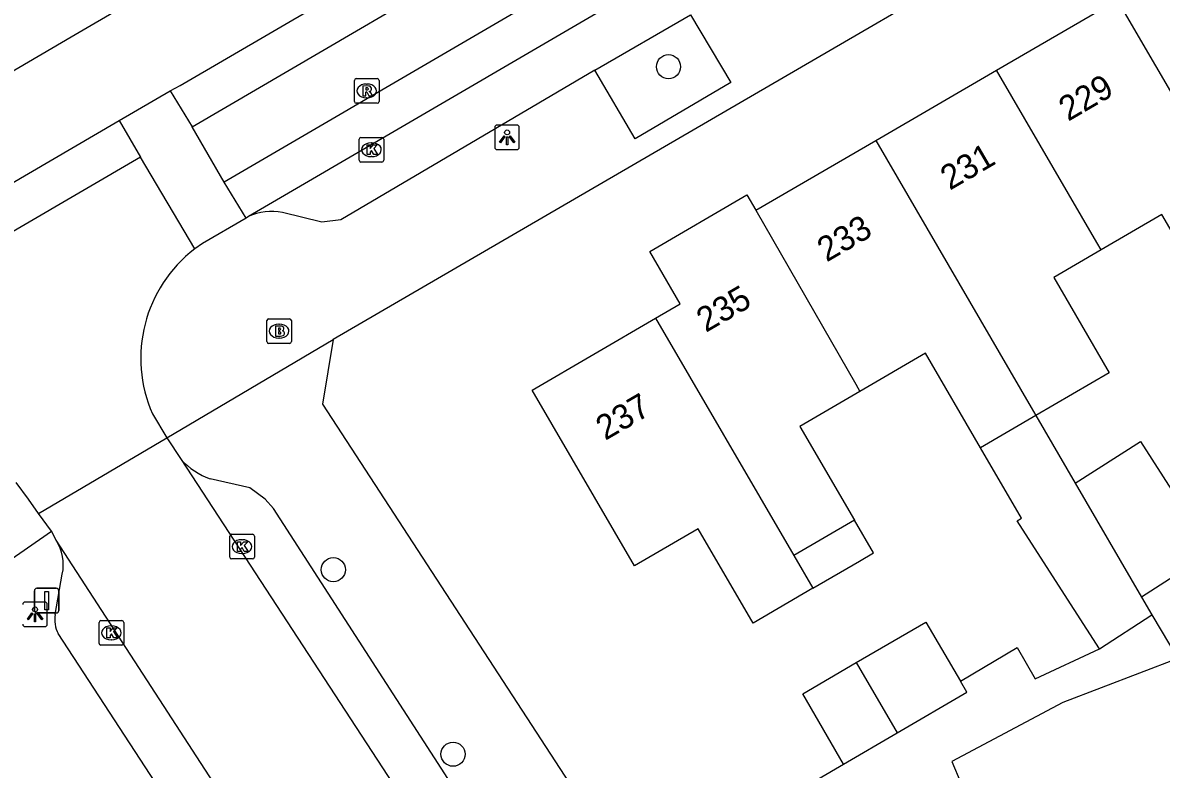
# Model space of a CAD drawing. Extents: x 158352 to 159489, y 383828 to 384597.
# Drawn here: x 158638.04 to 158684.3, y 384076.1 to 384106.43 of the extents above; entities that cross this region are included whole.
import ezdxf

# ---------------------------------------------------------------- set-up
doc = ezdxf.new("R2010")
doc.units = 0
for name, color, linetype in [('IMGEO_Afsluitpaal', 7, 'Continuous'), ('IMGEO_Boom', 7, 'Continuous'), ('IMGEO_Brandkraan', 7, 'Continuous'), ('IMGEO_Kolk', 7, 'Continuous'), ('IMGEO_Lichtpunt', 7, 'Continuous'), ('IMGEO_Pand', 7, 'Continuous'), ('IMGEO_Pand_nummerreeks', 7, 'Continuous'), ('IMGEO_Pand_overbouw', 7, 'Continuous'), ('IMGEO_Parkeervlak_open', 7, 'Continuous'), ('IMGEO_Rijbaan_lokaal_gesloten', 7, 'Continuous'), ('IMGEO_Rijbaan_lokaal_open', 7, 'Continuous'), ('IMGEO_Rioolput', 7, 'Continuous'), ('IMGEO_Voetpad_open', 7, 'Continuous')]:
    doc.layers.add(name, color=color, linetype=linetype)

msp = doc.modelspace()

# ---------------------------------------------------------------- linework, layer by layer
at = {"layer": 'IMGEO_Afsluitpaal'}
for p, q in [((158638.51, 384082.555), (158638.51, 384083.355)), ((158638.51, 384083.355), (158638.51, 384082.555)), ((158638.61, 384083.455), (158639.4, 384083.455)), ((158639.4, 384083.455), (158638.61, 384083.455)), ((158639.5, 384083.355), (158639.5, 384082.555)), ((158639.5, 384082.555), (158639.5, 384083.355)), ((158639.4, 384082.455), (158638.61, 384082.455)), ((158638.61, 384082.455), (158639.4, 384082.455))]:
    msp.add_line(p, q, dxfattribs=at)
msp.add_lwpolyline([(158638.93, 384083.33), (158639.08, 384083.33), (158639.08, 384082.58), (158638.93, 384082.58), (158638.93, 384083.33)], dxfattribs=at)
for centre, start, end in [((158638.61, 384083.355), 90, 180), ((158638.61, 384083.355), 90, 180), ((158639.4, 384083.355), 0, 90), ((158639.4, 384083.355), 360, 90), ((158638.61, 384082.555), 180, 270), ((158638.61, 384082.555), 180, 270), ((158639.4, 384082.555), 270, 0), ((158639.4, 384082.555), 270, 0)]:
    msp.add_arc(centre, 0.1, start, end, dxfattribs=at)
at = {"layer": 'IMGEO_Boom'}
for centre in [(158664.28, 384104.644), (158650.658, 384084.211), (158655.523, 384076.714)]:
    msp.add_circle(centre, 0.489, dxfattribs=at)
at = {"layer": 'IMGEO_Brandkraan'}
for p, q in [((158647.954, 384093.476), (158647.954, 384094.328)), ((158648.029, 384094.402), (158648.881, 384094.402)), ((158648.955, 384094.328), (158648.955, 384093.476)), ((158648.442, 384094.182), (158648.467, 384094.182)), ((158648.881, 384093.402), (158648.029, 384093.402)), ((158648.465, 384093.622), (158648.44, 384093.622))]:
    msp.add_line(p, q, dxfattribs=at)
for points in [[(158647.954, 384093.476), (158647.954, 384094.328)], [(158648.029, 384094.402), (158648.881, 384094.402)], [(158648.955, 384094.328), (158648.955, 384093.476)], [(158648.302, 384094.102), (158648.302, 384093.702), (158648.515, 384093.702)], [(158648.533, 384094.102), (158648.302, 384094.102)], [(158648.481, 384094.021), (158648.427, 384094.021), (158648.427, 384093.945)], [(158648.427, 384093.945), (158648.48, 384093.945)], [(158648.489, 384093.869), (158648.427, 384093.869), (158648.427, 384093.788)], [(158648.427, 384093.788), (158648.489, 384093.788)], [(158648.881, 384093.402), (158648.029, 384093.402)]]:
    msp.add_lwpolyline(points, dxfattribs=at)
for centre, radius, start, end in [((158648.031, 384094.326), 0.0765, 91.552, 178.448), ((158648.031, 384094.326), 0.0765, 91.552, 178.448), ((158648.879, 384094.326), 0.0765, 1.552, 88.448), ((158648.879, 384094.326), 0.0765, 1.552, 88.448), ((158648.482, 384093.983), 0.0379, 267.8285, 90.9355), ((158648.49, 384093.828), 0.0404, 269.8759, 90.5077), ((158648.537, 384093.957), 0.145, 59.4692, 91.5367), ((158648.562, 384094.004), 0.0922, 285.5137, 58.1501), ((158648.567, 384093.812), 0.105, 301.3115, 78.989), ((158648.031, 384093.478), 0.0765, 181.552, 268.448), ((158648.031, 384093.478), 0.0765, 181.552, 268.448), ((158648.521, 384093.953), 0.251, 268.6676, 293.5347), ((158648.879, 384093.478), 0.0765, 271.552, 358.448), ((158648.879, 384093.478), 0.0765, 271.552, 358.448)]:
    msp.add_arc(centre, radius, start, end, dxfattribs=at)
for centre, major_axis, ratio, start_param, end_param in [((158648.441, 384093.902), (-0.387, 0.002), 0.722429, 4.712389, 7.853982), ((158648.466, 384093.902), (-0.39, 0.002), 0.717154, 1.570796, 4.712389)]:
    msp.add_ellipse(centre, major_axis=major_axis, ratio=ratio, start_param=start_param, end_param=end_param, dxfattribs=at)
at = {"layer": 'IMGEO_Kolk'}
for p, q in [((158651.707, 384100.846), (158651.707, 384101.698)), ((158651.782, 384101.772), (158652.634, 384101.772)), ((158652.708, 384101.698), (158652.708, 384100.846)), ((158652.195, 384101.552), (158652.22, 384101.552)), ((158652.634, 384100.772), (158651.782, 384100.772)), ((158652.218, 384100.992), (158652.193, 384100.992)), ((158646.447, 384084.722), (158646.447, 384085.574)), ((158646.522, 384085.648), (158647.374, 384085.648)), ((158647.448, 384085.574), (158647.448, 384084.722)), ((158646.935, 384085.428), (158646.96, 384085.428)), ((158647.374, 384084.648), (158646.522, 384084.648)), ((158646.958, 384084.868), (158646.933, 384084.868)), ((158641.138, 384081.218), (158641.138, 384082.07)), ((158641.213, 384082.144), (158642.065, 384082.144)), ((158641.626, 384081.924), (158641.651, 384081.924)), ((158642.139, 384082.07), (158642.139, 384081.218)), ((158641.649, 384081.364), (158641.624, 384081.364)), ((158642.065, 384081.144), (158641.213, 384081.144))]:
    msp.add_line(p, q, dxfattribs=at)
for points in [[(158651.707, 384100.846), (158651.707, 384101.698)], [(158651.782, 384101.772), (158652.634, 384101.772)], [(158652.708, 384101.698), (158652.708, 384100.846)], [(158652.028, 384101.472), (158652.151, 384101.472), (158652.151, 384101.321), (158652.281, 384101.472), (158652.445, 384101.472), (158652.299, 384101.321), (158652.452, 384101.072), (158652.3, 384101.072), (158652.215, 384101.236), (158652.151, 384101.169), (158652.151, 384101.072), (158652.028, 384101.072), (158652.028, 384101.472)], [(158652.634, 384100.772), (158651.782, 384100.772)], [(158646.447, 384084.722), (158646.447, 384085.574)], [(158646.522, 384085.648), (158647.374, 384085.648)], [(158647.448, 384085.574), (158647.448, 384084.722)], [(158646.768, 384085.348), (158646.891, 384085.348), (158646.891, 384085.197), (158647.021, 384085.348), (158647.185, 384085.348), (158647.039, 384085.197), (158647.192, 384084.948), (158647.04, 384084.948), (158646.955, 384085.112), (158646.891, 384085.045), (158646.891, 384084.948), (158646.768, 384084.948), (158646.768, 384085.348)], [(158647.374, 384084.648), (158646.522, 384084.648)], [(158641.138, 384081.218), (158641.138, 384082.07)], [(158641.213, 384082.144), (158642.065, 384082.144)], [(158641.459, 384081.844), (158641.582, 384081.844), (158641.582, 384081.693), (158641.712, 384081.844), (158641.876, 384081.844), (158641.73, 384081.693), (158641.883, 384081.444), (158641.731, 384081.444), (158641.646, 384081.608), (158641.582, 384081.541), (158641.582, 384081.444), (158641.459, 384081.444), (158641.459, 384081.844)], [(158642.139, 384082.07), (158642.139, 384081.218)], [(158642.065, 384081.144), (158641.213, 384081.144)]]:
    msp.add_lwpolyline(points, dxfattribs=at)
for centre, start, end in [((158651.784, 384101.696), 91.552, 178.448), ((158651.784, 384101.696), 91.552, 178.448), ((158652.632, 384101.696), 1.552, 88.448), ((158652.632, 384101.696), 1.552, 88.448), ((158651.784, 384100.848), 181.552, 268.448), ((158651.784, 384100.848), 181.552, 268.448), ((158652.632, 384100.848), 271.552, 358.448), ((158652.632, 384100.848), 271.552, 358.448), ((158646.524, 384085.572), 91.552, 178.448), ((158646.524, 384085.572), 91.552, 178.448), ((158647.372, 384085.572), 1.552, 88.448), ((158647.372, 384085.572), 1.552, 88.448), ((158646.524, 384084.724), 181.552, 268.448), ((158646.524, 384084.724), 181.552, 268.448), ((158647.372, 384084.724), 271.552, 358.448), ((158647.372, 384084.724), 271.552, 358.448), ((158641.215, 384082.068), 91.552, 178.448), ((158641.215, 384082.068), 91.552, 178.448), ((158642.063, 384082.068), 1.552, 88.448), ((158642.063, 384082.068), 1.552, 88.448), ((158641.215, 384081.22), 181.552, 268.448), ((158641.215, 384081.22), 181.552, 268.448), ((158642.063, 384081.22), 271.552, 358.448), ((158642.063, 384081.22), 271.552, 358.448)]:
    msp.add_arc(centre, 0.0765, start, end, dxfattribs=at)
for centre, major_axis, ratio, start_param, end_param in [((158652.194, 384101.272), (-0.387, 0.002), 0.722429, 4.712389, 7.853982), ((158652.219, 384101.272), (-0.39, 0.002), 0.717154, 1.570796, 4.712389), ((158646.934, 384085.148), (-0.387, 0.002), 0.722429, 4.712389, 7.853982), ((158646.959, 384085.148), (-0.39, 0.002), 0.717154, 1.570796, 4.712389), ((158641.625, 384081.644), (-0.387, 0.002), 0.722429, 4.712389, 7.853982), ((158641.65, 384081.644), (-0.39, 0.002), 0.717154, 1.570796, 4.712389)]:
    msp.add_ellipse(centre, major_axis=major_axis, ratio=ratio, start_param=start_param, end_param=end_param, dxfattribs=at)
at = {"layer": 'IMGEO_Lichtpunt'}
for p, q in [((158657.221, 384102.177), (158657.221, 384101.37)), ((158657.221, 384102.177), (158657.221, 384101.37)), ((158658.123, 384102.272), (158657.315, 384102.272)), ((158658.123, 384102.272), (158657.315, 384102.272)), ((158658.217, 384101.37), (158658.217, 384102.177)), ((158658.217, 384101.37), (158658.217, 384102.177)), ((158657.315, 384101.276), (158658.123, 384101.276)), ((158657.315, 384101.276), (158658.123, 384101.276)), ((158638.939, 384082.894), (158638.131, 384082.894)), ((158638.939, 384082.894), (158638.131, 384082.894)), ((158639.033, 384081.992), (158639.033, 384082.799)), ((158639.033, 384081.992), (158639.033, 384082.799)), ((158638.131, 384081.898), (158638.939, 384081.898)), ((158638.131, 384081.898), (158638.939, 384081.898))]:
    msp.add_line(p, q, dxfattribs=at)
for points in [[(158657.595, 384101.841), (158657.634, 384101.813), (158657.446, 384101.551), (158657.408, 384101.578), (158657.595, 384101.841)], [(158657.697, 384101.793), (158657.744, 384101.793), (158657.744, 384101.471), (158657.697, 384101.471), (158657.697, 384101.793)], [(158657.807, 384101.813), (158657.845, 384101.84), (158658.032, 384101.578), (158657.993, 384101.55), (158657.807, 384101.813)], [(158638.411, 384082.463), (158638.45, 384082.435), (158638.262, 384082.173), (158638.224, 384082.2), (158638.411, 384082.463)], [(158638.513, 384082.415), (158638.56, 384082.415), (158638.56, 384082.093), (158638.513, 384082.093), (158638.513, 384082.415)], [(158638.623, 384082.435), (158638.661, 384082.462), (158638.848, 384082.2), (158638.809, 384082.172), (158638.623, 384082.435)]]:
    msp.add_lwpolyline(points, dxfattribs=at)
for centre in [(158657.72, 384101.975), (158638.536, 384082.597)]:
    msp.add_circle(centre, 0.0994, dxfattribs=at)
for centre, start, end in [((158657.315, 384102.177), 90, 180), ((158657.315, 384102.177), 90, 180), ((158658.123, 384102.177), 0, 90), ((158658.123, 384102.177), 0, 90), ((158657.315, 384101.37), 180, 270), ((158657.315, 384101.37), 180, 270), ((158658.123, 384101.37), 270, 0), ((158658.123, 384101.37), 270, 360), ((158638.131, 384082.799), 90, 180), ((158638.131, 384082.799), 90, 180), ((158638.939, 384082.799), 0, 90), ((158638.939, 384082.799), 0, 90), ((158638.131, 384081.992), 180, 270), ((158638.131, 384081.992), 180, 270), ((158638.939, 384081.992), 270, 0), ((158638.939, 384081.992), 270, 360)]:
    msp.add_arc(centre, 0.0946, start, end, dxfattribs=at)
at = {"layer": 'IMGEO_Pand'}
for points in [[(158677.609, 384104.504), (158682.517, 384107.363)], [(158682.517, 384107.363), (158688.839, 384096.51), (158689.03, 384096.182)], [(158672.701, 384101.645), (158677.609, 384104.504)], [(158681.861, 384097.204), (158681.687, 384097.502), (158677.609, 384104.504)], [(158667.836, 384098.811), (158672.701, 384101.645)], [(158672.701, 384101.645), (158679.021, 384090.795), (158679.211, 384090.469)], [(158663.758, 384094.428), (158664.755, 384095.009), (158663.516, 384097.136), (158667.47, 384099.439), (158667.836, 384098.811)], [(158667.836, 384098.811), (158671.895, 384091.744), (158672.062, 384091.456)], [(158689.03, 384096.182), (158686.593, 384094.763), (158684.333, 384098.644), (158681.861, 384097.204)], [(158681.861, 384097.204), (158679.936, 384096.083), (158682.194, 384092.207), (158679.211, 384090.469)], [(158669.376, 384084.785), (158670.15, 384083.456), (158667.715, 384082.037), (158665.479, 384085.873), (158662.904, 384084.372), (158658.746, 384091.509), (158663.758, 384094.428)], [(158663.758, 384094.428), (158669.376, 384084.785)], [(158676.961, 384089.159), (158674.72, 384093.005), (158672.062, 384091.456)], [(158672.062, 384091.456), (158669.621, 384090.034), (158671.842, 384086.22), (158669.376, 384084.785)], [(158679.211, 384090.469), (158676.961, 384089.159)], [(158679.211, 384090.469), (158680.813, 384087.719)], [(158681.793, 384080.999), (158680.254, 384083.394), (158678.45, 384086.2), (158678.621, 384086.31), (158676.961, 384089.159)], [(158680.813, 384087.719), (158683.463, 384089.422), (158686.354, 384084.927), (158683.506, 384083.096)], [(158680.813, 384087.719), (158683.506, 384083.096)], [(158683.506, 384083.096), (158683.928, 384082.372)], [(158681.793, 384080.999), (158683.928, 384082.372)], [(158671.91, 384080.435), (158674.74, 384082.084), (158676.142, 384079.676)], [(158671.394, 384076.315), (158669.733, 384079.167), (158671.91, 384080.435)], [(158671.91, 384080.435), (158673.571, 384077.583)], [(158673.571, 384077.583), (158676.401, 384079.232), (158676.142, 384079.676)], [(158671.394, 384076.315), (158673.571, 384077.583)]]:
    msp.add_lwpolyline(points, dxfattribs=at)
at = {"layer": 'IMGEO_Pand_overbouw'}
msp.add_lwpolyline([(158672.615, 384084.892), (158671.842, 384086.22), (158669.376, 384084.785), (158670.15, 384083.456), (158672.036, 384084.555)], close=True, dxfattribs=at)
at = {"layer": 'IMGEO_Parkeervlak_open'}
for points in [[(158661.287, 384104.498), (158665.178, 384106.745)], [(158639.355, 384082.394), (158639.644, 384084.029)], [(158652.371, 384061.856), (158639.475, 384081.612)]]:
    msp.add_lwpolyline(points, dxfattribs=at)
for centre, radius, start, end in [((158637.826, 384084.41), 1.858, 348.1673, 32.6465), ((158640.615, 384082.187), 1.277, 170.6828, 206.7655)]:
    msp.add_arc(centre, radius, start, end, dxfattribs=at)
at = {"layer": 'IMGEO_Rijbaan_lokaal_gesloten'}
for points in [[(158644.915, 384102.204), (158736.245, 384155.536)], [(158737.545, 384153.226), (158646.22, 384099.951)], [(158738.379, 384151.745), (158647.204, 384098.556)], [(158644.032, 384103.668), (158644.427, 384103.877), (158655.57, 384110.383), (158659.63, 384112.744)], [(158627.36, 384093.946), (158641.961, 384102.46)], [(158647.204, 384098.556), (158647.12, 384098.492)]]:
    msp.add_lwpolyline(points, dxfattribs=at)
at = {"layer": 'IMGEO_Rijbaan_lokaal_open'}
for points in [[(158641.961, 384102.46), (158644.032, 384103.668)], [(158644.032, 384103.668), (158644.915, 384102.204)], [(158641.961, 384102.46), (158642.815, 384100.969)], [(158646.22, 384099.951), (158644.915, 384102.204)], [(158642.815, 384100.969), (158628.258, 384092.479)], [(158645.024, 384097.242), (158642.815, 384100.969)], [(158647.12, 384098.492), (158646.22, 384099.951)], [(158647.12, 384098.492), (158645.336, 384097.464), (158645.024, 384097.242)], [(158643.313, 384090.537), (158643.898, 384089.569)], [(158638.682, 384086.499), (158643.898, 384089.569)], [(158643.898, 384089.569), (158644.468, 384088.685)], [(158644.468, 384088.685), (158659.101, 384066.295), (158660.748, 384067.316)], [(158638.682, 384086.499), (158638.27, 384087.073), (158637.764, 384087.748)], [(158639.205, 384085.77), (158638.682, 384086.499)], [(158639.39, 384085.412), (158639.205, 384085.77)], [(158652.371, 384061.856), (158654.012, 384062.903), (158639.39, 384085.412)]]:
    msp.add_lwpolyline(points, dxfattribs=at)
msp.add_arc((158648.417, 384092.805), 5.585, 127.4085, 203.9608, dxfattribs=at)
at = {"layer": 'IMGEO_Rioolput'}
for p, q in [((158651.514, 384103.234), (158651.514, 384104.086)), ((158651.589, 384104.16), (158652.441, 384104.16)), ((158652.002, 384103.94), (158652.027, 384103.94)), ((158652.515, 384104.086), (158652.515, 384103.234)), ((158652.441, 384103.16), (158651.589, 384103.16)), ((158652.025, 384103.38), (158652, 384103.38))]:
    msp.add_line(p, q, dxfattribs=at)
for points in [[(158651.514, 384103.234), (158651.514, 384104.086)], [(158651.589, 384104.16), (158652.441, 384104.16)], [(158652.515, 384104.086), (158652.515, 384103.234)], [(158652.103, 384103.858), (158651.851, 384103.86), (158651.851, 384103.46)], [(158651.851, 384103.46), (158651.975, 384103.46), (158651.975, 384103.622), (158651.986, 384103.622)], [(158652.029, 384103.779), (158651.975, 384103.779), (158651.975, 384103.698)], [(158651.975, 384103.698), (158652.027, 384103.698)], [(158652.033, 384103.593), (158652.104, 384103.46), (158652.244, 384103.46), (158652.179, 384103.586)], [(158652.441, 384103.16), (158651.589, 384103.16)]]:
    msp.add_lwpolyline(points, dxfattribs=at)
for centre, radius, start, end in [((158651.591, 384104.084), 0.0765, 91.552, 178.448), ((158651.591, 384104.084), 0.0765, 91.552, 178.448), ((158652.439, 384104.084), 0.0765, 1.552, 88.448), ((158652.439, 384104.084), 0.0765, 1.552, 88.448), ((158651.985, 384103.569), 0.0533, 26.0293, 88.6989), ((158652.011, 384103.887), 0.19, 274.7715, 282.9687), ((158652.035, 384103.683), 0.0964, 77.0061, 93.1865), ((158652.049, 384103.74), 0.0378, 276.6634, 79.6772), ((158652.102, 384103.748), 0.109, 350.3612, 89.416), ((158652.1, 384103.748), 0.112, 277.5842, 350.9817), ((158652.084, 384103.533), 0.108, 29.5134, 73.7905), ((158651.591, 384103.236), 0.0765, 181.552, 268.448), ((158651.591, 384103.236), 0.0765, 181.552, 268.448), ((158652.439, 384103.236), 0.0765, 271.552, 358.448), ((158652.439, 384103.236), 0.0765, 271.552, 358.448)]:
    msp.add_arc(centre, radius, start, end, dxfattribs=at)
for centre, major_axis, ratio, start_param, end_param in [((158652.001, 384103.66), (-0.387, 0.002), 0.722429, 4.712389, 7.853982), ((158652.026, 384103.66), (-0.39, 0.002), 0.717154, 1.570796, 4.712389)]:
    msp.add_ellipse(centre, major_axis=major_axis, ratio=ratio, start_param=start_param, end_param=end_param, dxfattribs=at)
at = {"layer": 'IMGEO_Voetpad_open'}
for points in [[(158695.294, 384119.527), (158650.651, 384093.56)], [(158644.581, 384108.521), (158640.005, 384105.85), (158634.558, 384102.668)], [(158665.178, 384106.745), (158666.82, 384104.008), (158662.922, 384101.718), (158661.287, 384104.498)], [(158661.287, 384104.498), (158650.96, 384098.425), (158650.189, 384098.335), (158648.598, 384098.717)], [(158643.898, 384089.569), (158650.651, 384093.56)], [(158650.651, 384093.56), (158650.222, 384090.931), (158662.957, 384071.401)], [(158660.748, 384067.316), (158648.224, 384086.702), (158647.894, 384087.075), (158647.267, 384087.536), (158645.649, 384087.897)], [(158612.294, 384067.106), (158639.205, 384085.77)], [(158683.928, 384082.372), (158684.984, 384080.601), (158680.306, 384078.814), (158675.801, 384076.42), (158676.156, 384075.548)], [(158676.142, 384079.676), (158678.45, 384081.043), (158679.181, 384079.783), (158681.793, 384080.999)], [(158662.957, 384071.401), (158669.142, 384075.003), (158671.394, 384076.315)]]:
    msp.add_lwpolyline(points, dxfattribs=at)
for centre, radius, start, end in [((158648.146, 384096.514), 2.249, 78.4086, 114.7678), ((158646.745, 384090.819), 3.12, 223.1381, 249.437)]:
    msp.add_arc(centre, radius, start, end, dxfattribs=at)

# ---------------------------------------------------------------- texts
at = {"layer": 'IMGEO_Pand_nummerreeks'}
for s, rotation, p in [('229', 30.221, (158680.522, 384102.405)), ('231', 30.221, (158675.712, 384099.603)), ('233', 30.221, (158670.706, 384096.687)), ('235', 30.2235, (158665.798, 384093.828)), ('237', 30.2178, (158661.71, 384089.441))]:
    msp.add_text(s, height=1, rotation=rotation, dxfattribs=at).set_placement(p)

doc.saveas('drawing.dxf')
